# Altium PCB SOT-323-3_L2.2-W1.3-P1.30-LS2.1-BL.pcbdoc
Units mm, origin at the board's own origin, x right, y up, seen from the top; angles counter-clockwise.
Board outline 15.38 x 15.73 mm, 2 copper layers (Top Layer, Bottom Layer), stack 0 mm thick; 1 components, 0 nets, 3 pads, 0 vias.
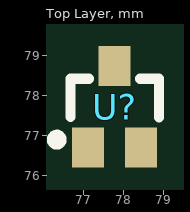
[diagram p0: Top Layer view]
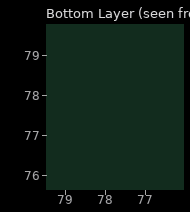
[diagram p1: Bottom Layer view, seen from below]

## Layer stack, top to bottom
Top Layer: signal copper (thickness not stored)
Bottom Layer: signal copper (thickness not stored)

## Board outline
85.229,69.85 69.85,69.85 69.85,85.582 85.229,85.582

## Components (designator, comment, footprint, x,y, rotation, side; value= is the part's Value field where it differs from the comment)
U? "" SOT-323-3_L2.2-W1.3-P1.30-LS2.1-BL 77.769,77.716 r0 top

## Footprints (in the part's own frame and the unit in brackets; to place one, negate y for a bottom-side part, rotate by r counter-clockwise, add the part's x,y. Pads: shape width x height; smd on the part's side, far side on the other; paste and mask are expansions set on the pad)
SOT-323-3_L2.2-W1.3-P1.30-LS2.1-BL [mm]
  rect 0.8x1 smd: 1(-0.66,-1.016) 2(0.66,-1.016) 3(0,1.016)
  silkscreen extent -1.57,-0.95 1.11,0.7

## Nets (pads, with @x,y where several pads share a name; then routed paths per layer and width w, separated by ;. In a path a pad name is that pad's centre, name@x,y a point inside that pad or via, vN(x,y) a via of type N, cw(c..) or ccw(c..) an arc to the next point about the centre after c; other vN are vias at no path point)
pads on no net: U?.1 U?.2 U?.3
